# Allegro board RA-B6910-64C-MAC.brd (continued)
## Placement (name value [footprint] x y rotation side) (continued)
C3171  0.1uF/25V  [C0402]  230.55 144.8 0 bottom
C3172  0.1uF/25V  [C0402]  168.58 162.84 0 bottom
C3173  10uF/6.3V  [C0402]  217.23 179.32 270 top
C3174  0.1uF/25V  [C0402]  153.1 139.32 90 top
C3175  0.1uF/25V  [C0402]  227.56 166.9 0 bottom
C3176  0.1uF/25V  [C0402]  213.53 161.84 180 bottom
C3177  0.1uF/25V  [C0402]  215.55 128.82 180 bottom
C3178  0.1uF/25V  [C0402]  165.53 121.83 0 bottom
C3179  0.1uF/25V  [C0402]  226.56 113.81 0 bottom
C3180  47uF/6.3V  [C0805]  257.11 129.79 0 top
C3181  10uF/6.3V  [C0402]  201.54 130.83 0 bottom
C3182  47uF/6.3V  [C0805]  257.11 125.22 0 top
C3183  0.1uF/25V  [C0402]  221.56 168.86 0 bottom
C3184  0.1uF/25V  [C0402]  191.56 120.85 180 bottom
C3185  0.1uF/25V  [C0402]  199.04 160.32 270 bottom
C3186  0.1uF/25V  [C0402]  165.56 144.86 0 bottom
C3187  0.1uF/25V  [C0402]  176.64 139.73 0 bottom
C3188  0.1uF/25V  [C0402]  188.57 167.84 0 bottom
C3189  0.1uF/25V  [C0402]  181.05 158.33 90 bottom
C3190  1uF/25V  [C0402]  199.54 152.83 0 bottom
C3191  47uF/6.3V  [C0805]  257.11 120.65 0 top
C3192  0.1uF/25V  [C0402]  170.53 160.84 0 bottom
C3194  0.1uF/25V  [C0402]  205.05 167.34 270 bottom
C3195  0.1uF/25V  [C0402]  213.55 132.82 0 bottom
C3196  0.1uF/25V  [C0402]  153.1 137.16 270 top
C3197  0.1uF/25V  [C0402]  213.55 144.82 0 bottom
C3317  0.1uF/25V  [C0402]  213.54 142.82 0 bottom
C3318  0.1uF/25V  [C0402]  211.57 125.83 180 bottom
C3319  0.1uF/25V  [C0402]  183.53 125.83 0 bottom
C3320  0.1uF/25V  [C0402]  181.05 154.33 90 bottom
C3321  0.1uF/25V  [C0402]  181.54 150.83 0 bottom
C3322  0.1uF/25V  [C0402]  209.56 153.85 0 bottom
C3323  0.1uF/25V  [C0402]  187.55 124.81 0 bottom
C3324  0.1uF/25V  [C0402]  181.55 147.83 0 bottom
C3325  0.1uF/25V  [C0402]  213.55 128.83 0 bottom
C3326  0.1uF/25V  [C0402]  213.55 145.82 0 bottom
C3327  0.1uF/25V  [C0402]  181.53 144.83 0 bottom
C3328  0.1uF/25V  [C0402]  189.55 124.83 0 bottom
C3329  0.1uF/25V  [C0402]  205.54 152.83 180 bottom
C3330  0.1uF/25V  [C0402]  213.55 131.82 0 bottom
C3331  0.1uF/25V  [C0402]  181.53 141.83 0 bottom
C3332  0.1uF/25V  [C0402]  195.55 125.83 0 bottom
C3333  0.1uF/25V  [C0402]  213.55 148.82 180 bottom
C3334  0.1uF/25V  [C0402]  181.55 136.87 180 bottom
C3335  0.1uF/25V  [C0402]  190.05 154.33 90 bottom
C3336  0.1uF/25V  [C0402]  203.54 125.83 0 bottom
C3337  0.1uF/25V  [C0402]  213.55 134.82 0 bottom
C3338  0.1uF/25V  [C0402]  181.55 133.87 0 bottom
C3339  0.1uF/25V  [C0402]  213.55 151.82 180 bottom
C3340  0.1uF/25V  [C0402]  205.55 124.82 0 bottom
C3341  0.1uF/25V  [C0402]  181.55 130.85 0 bottom
C3342  0.1uF/25V  [C0402]  188.05 154.33 90 bottom
C3343  0.1uF/25V  [C0402]  213.55 139.82 0 bottom
C3344  0.1uF/25V  [C0402]  209.55 124.82 0 bottom
C3345  0.1uF/25V  [C0402]  181.55 127.85 0 bottom
C3346  0.1uF/25V  [C0402]  213.58 152.85 0 bottom
C3347  0.1uF/25V  [C0402]  184.05 154.33 90 bottom
C3368  104  [C0603]  72.07 193.55 0 bottom
C3369  10uF/25V  [C0805]  58.74 183.51 270 bottom
C3370  X  [C1206]  423.48 56 270 top
C3371  X  [C1206]  420.69 56 270 top
C3420  100uF/6.3V  [C1206]  327.98 199.51 0 top
C3421  0.1uF/25V  [C0402]  192.6 179.96 270 top
C3422  0.1uF/25V  [C0402]  193.61 179.96 270 top
C3423  0.1uF/25V  [C0402]  199.71 174.75 270 bottom
C3424  0.1uF/25V  [C0402]  200.85 174.75 270 bottom
C3425  10uF/6.3V  [C0402]  301.18 211.71 180 top
C3426  1uF/25V  [C0402]  290.46 213.84 180 top
C3427  0.1uF/25V  [C0402]  294.91 212.82 0 top
C3428  103  [C0402]  294.91 211.68 0 top
C3429  102  [C0402]  298.89 200.02 0 top
C3430  0.1uF/25V  [C0402]  292.67 215.14 90 bottom
C3431  100P  [C0402]  295.16 215.11 90 bottom
C3432  103  [C0402]  293.89 215.11 90 bottom
C3433  102  [C0402]  295.85 215.14 0 top
C3434  103  [C0402]  292.8 197.61 90 top
C3435  102  [C0402]  293.94 197.61 90 top
C3436  X  [C0402]  306.34 205.33 180 bottom
C3437  10uF/6.3V  [C0402]  296.3 215.11 270 bottom
C3438  100P  [C0402]  297.45 215.11 270 bottom
C3439  22nF  [C0402]  300.8 215.01 270 top
C3440  1uF/25V  [C0402]  301.18 204.85 0 top
C3441  0.1uF/25V  [C0402]  298.21 205.33 90 top
C3442  103  [C0402]  299.35 205.33 90 top
C3443  1uF/25V  [C0402]  294.78 205.33 90 top
C3444  0.1uF/25V  [C0402]  297.07 205.33 90 top
C3445  103  [C0402]  295.92 205.33 90 top
C3446  103  [C0402]  287.54 209.9 180 bottom
C3447  103  [C0402]  287.54 208.38 180 bottom
C3448  1uF/25V  [C0402]  290.46 204.57 180 top
C3449  0.1uF/25V  [C0402]  290.46 205.71 180 top
C3450  103  [C0402]  287.54 212.82 180 bottom
C3451  103  [C0402]  294.91 207.11 0 top
C3452  1uF/25V  [C0402]  290.46 208 180 top
C3453  0.1uF/25V  [C0402]  290.46 206.86 180 top
C3454  103  [C0402]  294.91 208.25 0 top
C3455  103  [C0402]  287.54 211.05 180 bottom
C3456  1uF/25V  [C0402]  290.46 210.28 180 top
C3457  0.1uF/25V  [C0402]  290.46 209.14 180 top
C3458  103  [C0402]  294.91 209.4 0 top
C3459  1uF/25V  [C0402]  290.46 212.57 180 top
C3460  0.1uF/25V  [C0402]  290.46 211.43 180 top
C3461  103  [C0402]  294.91 210.54 0 top
C3462  10uF/6.3V  [C0402]  321.07 205.76 180 top
C3463  0.1uF/25V  [C0402]  321.07 207.03 180 top
C3464  103  [C0402]  321.07 208.3 180 top
C3465  0.1uF/25V  [C0402]  316.52 201.7 180 top
C3466  X  [C0603]  311.29 202.03 0 bottom
C3467  X  [C0603]  311.29 203.93 0 bottom
C3468  1uF/25V  [C0402]  301.18 213.23 180 top
C3469  0.1uF/25V  [C0402]  301.18 210.56 180 top
C3470  1uF/25V  [C0402]  301.18 208.28 180 top
C3471  0.1uF/25V  [C0402]  301.18 209.42 180 top
C3472  1uF/25V  [C0402]  301.18 205.99 180 top
C3473  0.1uF/25V  [C0402]  301.18 207.13 180 top
C3474  X  [C0402]  309 206.6 0 bottom
C3475  X  [C0402]  43.85 157.99 0 top
C3476  X  [C0402]  43.85 159.26 0 top
C3477  X  [C0402]  43.85 156.84 0 top
C3478  X  [C0402]  45.91 163.45 270 top
C3479  X  [C0402]  40.7 163.7 0 top
C3480  X  [C0402]  116.27 218.56 270 bottom
C3481  X  [C0402]  88.33 203.07 270 top
C3482  X  [C0402]  89.34 203.07 270 top
C3483  X  [C0402]  91.38 203.07 270 top
C3484  X  [C0402]  90.36 203.07 270 top
C3485  X  [C0402]  92.39 203.07 270 top
C3486  X  [C0402]  93.41 203.07 270 top
C3487  X  [C0402]  87.31 203.07 270 top
C3488  104  [C0603]  57.47 206.37 90 bottom
C3489  1uF/25V  [C0805]  65.09 205.99 90 bottom
C3490  10uF/25V  [C0805]  62.42 205.99 90 bottom
C3491  X  [C0402]  70.8 217.29 0 bottom
C3492  X  [C0402]  70.8 212.21 0 bottom
C3493  X  [C0402]  70.8 216.28 0 bottom
C3494  X  [C0402]  70.8 211.2 0 bottom
C3495  X  [C0402]  70.8 210.18 0 bottom
C3496  X  [C0402]  70.8 214.25 0 bottom
C3497  X  [C0402]  70.8 213.23 0 bottom
C3498  X  [C0402]  70.8 215.26 0 bottom
C3499  0.1uF/25V  [C0402]  20.99 191.97 270 bottom
C3500  0.1uF/25V  [C0402]  11.75 191.89 270 bottom
C3501  0.1uF/25V  [C0402]  35.24 194.31 0 bottom
C3502  0.1uF/25V  [C0402]  29.65 191.89 270 bottom
C3503  X  [C0603]  411.29 76.58 0 top
C3504  X  [C0603]  406.46 76.58 180 top
C3505  X  [C0402]  406.08 211.88 180 top
C3506  X  [C0402]  408.24 211.88 0 top
C3507  X  [C0402]  403.92 211.88 0 top
C3508  X  [C0402]  397.45 211.88 180 top
C3509  X  [C0402]  393.13 211.88 180 top
C3510  X  [C0402]  401.76 211.88 180 top
C3511  X  [C0402]  399.61 211.88 0 top
C3512  X  [C0402]  395.29 211.88 0 top
C3513  103  [C0402]  423.61 13.81 270 top
C3514  1uF/25V  [C0402]  394.53 21.71 180 top
C3515  0.1uF/25V  [C0402]  394.53 22.86 180 top
C3516  33uF/10V  [C1206]  387.41 212.95 90 bottom
C3517  0.1uF/25V  [C0402]  32.19 173.61 90 top
C3518  X  [C0402]  33.34 173.61 90 top
C3519  0.1uF/25V  [C0402]  199.61 203.15 270 top
C3520  0.1uF/25V  [C0402]  400.19 101.95 180 top
C3521  102  [C0402]  27.24 165.22 90 bottom
C3522  10uF/6.3V  [C0402]  16.6 165.86 0 bottom
C3523  0.1uF/25V  [C0402]  16.19 147.83 90 top
C3524  0.1uF/25V  [C0402]  30.04 152.63 0 bottom
C3525  0.1uF/25V  [C0402]  18.86 167.26 270 bottom
C3526  0.1uF/25V  [C0402]  31.81 167.38 270 bottom
C3527  10uF/6.3V  [C0402]  31.05 155.32 0 bottom
C3528  10uF/6.3V  [C0402]  32.22 150.37 90 bottom
C3529  0.1uF/25V  [C0402]  32.98 164.46 180 bottom
C3530  0.1uF/25V  [C0402]  16.6 151 0 bottom
C3531  0.1uF/25V  [C0402]  18.99 147.83 90 bottom
C3532  0.1uF/25V  [C0402]  30.95 163.83 0 bottom
C3533  10uF/6.3V  [C0402]  16.6 152.78 0 bottom
C3534  0.1uF/25V  [C0402]  23.56 159 180 bottom
C3535  0.1uF/25V  [C0402]  24.83 155.45 90 bottom
C3536  10uF/6.3V  [C0402]  21.4 167.38 270 bottom
C3537  0.1uF/25V  [C0402]  33.11 156.72 180 bottom
C3538  1uF/25V  [C0402]  19.75 165.35 180 bottom
C3539  10uF/6.3V  [C0402]  32.96 165.73 180 bottom
C3540  0.1uF/25V  [C0402]  24.83 160.53 90 bottom
C3541  0.1uF/25V  [C0402]  16.57 167.64 0 bottom
C3542  0.1uF/25V  [C0402]  33.24 152.02 180 bottom
C3543  0.1uF/25V  [C0402]  27.75 159 180 bottom
C3544  0.1uF/25V  [C0402]  21.53 159 0 bottom
C3545  0.1uF/25V  [C0402]  24.83 157.48 270 bottom
C3546  0.1uF/25V  [C0402]  16.57 154.28 0 bottom
C3547  0.1uF/25V  [C0402]  30.54 147.83 90 top
C3548  1uF/25V  [C0402]  30.95 162.68 180 bottom
C3549  10uF/6.3V  [C0402]  19.65 151.69 180 bottom
C3550  10uF/6.3V  [C0402]  34.48 167.89 180 bottom
C3551  0.1uF/25V  [C0402]  18.99 147.83 90 top
C3552  0.1uF/25V  [C0402]  19.65 152.7 180 bottom
C3553  0.1uF/25V  [C0402]  31.05 154.18 0 bottom
C3554  0.1uF/25V  [C0402]  18.38 164.08 90 bottom
C3555  10uF/6.3V  [C0402]  28.66 150.49 90 bottom
C3556  0.1uF/25V  [C0402]  25.72 159 0 bottom
C3557  1uF/25V  [C0402]  18.5 154.18 270 bottom
C3558  10uF/6.3V  [C0402]  30.67 147.83 90 bottom
C3560  10uF/6.3V  [C0402]  408.09 176.27 90 bottom
C3561  0.1uF/25V  [C0402]  396.81 174.55 180 bottom
C3562  0.1uF/25V  [C0402]  413.19 173.48 180 top
C3563  0.1uF/25V  [C0402]  402.02 177.16 90 bottom
C3564  0.1uF/25V  [C0402]  393 189.35 270 bottom
C3565  10uF/6.3V  [C0402]  413.19 186.31 0 top
C3566  10uF/6.3V  [C0402]  399.12 172.34 90 bottom
C3567  0.1uF/25V  [C0402]  410.02 189.23 270 bottom
C3568  0.1uF/25V  [C0402]  393.76 174.62 0 bottom
C3569  0.1uF/25V  [C0402]  405.83 172.34 90 bottom
C3570  0.1uF/25V  [C0402]  410.27 186.31 180 bottom
C3571  10uF/6.3V  [C0402]  396.81 173.53 180 bottom
C3572  0.1uF/25V  [C0402]  393.76 177.06 0 bottom
C3573  1uF/25V  [C0402]  395.67 176.02 270 bottom
C3574  10uF/6.3V  [C0402]  396.05 189.1 270 bottom
C3575  10uF/6.3V  [C0402]  410.4 173.86 180 bottom
C3576  0.1uF/25V  [C0402]  393.76 172.84 0 bottom
C3577  0.1uF/25V  [C0402]  395.54 185.93 90 bottom
C3578  0.1uF/25V  [C0402]  390.84 174.37 0 top
C3579  0.1uF/25V  [C0402]  410.27 178.56 180 bottom
C3580  0.1uF/25V  [C0402]  409.38 172.21 90 bottom
C3581  0.1uF/25V  [C0402]  402.02 182.37 90 bottom
C3582  0.1uF/25V  [C0402]  400.85 180.82 180 bottom
C3583  0.1uF/25V  [C0402]  398.82 180.82 0 bottom
C3584  0.1uF/25V  [C0402]  404.91 180.82 180 bottom
C3585  0.1uF/25V  [C0402]  402.88 180.82 0 bottom
C3586  1uF/25V  [C0402]  408.11 184.53 180 bottom
C3587  10uF/6.3V  [C0402]  396.18 169.67 90 top
C3588  10uF/6.3V  [C0402]  396.94 187.32 180 bottom
C3589  0.1uF/25V  [C0402]  407.2 174.47 0 bottom
C3590  0.1uF/25V  [C0402]  413.19 186.31 180 bottom
C3591  0.1uF/25V  [C0402]  407.1 187.32 0 bottom
C3592  0.1uF/25V  [C0402]  393.76 187.7 0 bottom
C3593  10uF/6.3V  [C0402]  413.19 170.56 180 top
C3594  0.1uF/25V  [C0402]  401.99 179.3 270 bottom
C3595  1uF/25V  [C0402]  409.11 176.27 270 bottom
C3596  10uF/6.3V  [C0402]  408.11 185.67 0 bottom
C3597  100uF/6.3V  [C1206]  327.85 167.89 0 top
C3598  100uF/6.3V  [C1206]  328.1 189.61 0 bottom
C3599  100uF/6.3V  [C1206]  327.85 188.59 0 top
C3600  100uF/6.3V  [C1206]  327.85 178.31 0 top
C3601  100uF/6.3V  [C1206]  327.98 196.72 0 top
C3602  104  [C0603]  384.37 198.75 90 bottom
C3603  0.47uF  [C0603]  279.21 217.68 90 top
C3604  10uF/25V  [C0805]  272.48 213.87 270 top
C3605  0.1uF/25V  [C0402]  275.4 213.99 270 top
C3606  0.47uF  [C0603]  279.46 207.64 90 top
C3607  X  [C0402]  391.99 198.88 270 top
C3608  1uF/25V  [C0402]  274.26 213.99 270 top
C3609  0.1uF/25V  [C0402]  273.24 210.31 90 top
C3610  10uF/6.3V  [C0402]  275.78 210.31 90 top
C3611  1uF/25V  [C0402]  274.51 210.31 90 top
C3612  104  [C0603]  380.94 197.74 90 top
C3613  10uF/25V  [C0805]  378.9 197.74 90 bottom
C3614  10uF/25V  [C0805]  378.9 197.74 90 top
C3615  22uF/25V  [C0805]  377.51 202.56 270 bottom
C3616  22uF/25V  [C0805]  379.92 202.56 270 bottom
C3617  1uF/25V  [C0402]  378.78 201.8 270 top
C3618  0.1uF/25V  [C0402]  380.3 201.8 90 top
C3619  104  [C0603]  366.08 117.35 180 bottom
C3620  X  [C0402]  365.95 124.97 0 top
C3621  104  [C0603]  149.16 210.69 90 bottom
C3622  104  [C0603]  367.09 113.92 180 top
C3623  10uF/25V  [C0805]  367.09 111.88 180 top
C3624  10uF/25V  [C0805]  367.09 111.88 180 bottom
C3625  22uF/6.3V  [C0603]  362.65 110.61 0 bottom
C3626  22uF/6.3V  [C0603]  362.65 113.15 0 bottom
C3627  1uF/25V  [C0402]  363.03 111.76 0 top
C3628  0.1uF/25V  [C0402]  363.03 113.28 180 top
C3629  X  [C0402]  154.62 210.56 270 top
C3630  104  [C0603]  145.35 209.67 90 top
C3631  10uF/25V  [C0805]  143.32 209.67 90 bottom
C3632  10uF/25V  [C0805]  143.32 209.67 90 top
C3633  22uF/6.3V  [C0603]  144.97 213.74 270 bottom
C3634  22uF/6.3V  [C0603]  143.19 213.74 270 bottom
C3635  1uF/25V  [C0402]  143.19 213.74 270 top
C3636  0.1uF/25V  [C0402]  144.97 213.61 90 top
C3637  104  [C0603]  378.9 213.61 90 bottom
C3638  X  [C0402]  386.61 212.72 270 top
C3639  104  [C0603]  375.48 212.6 90 top
C3640  10uF/25V  [C0805]  373.44 212.6 90 top
C3641  10uF/25V  [C0805]  373.44 212.6 90 bottom
C3642  22uF/6.3V  [C0603]  374.71 217.04 270 bottom
C3643  22uF/6.3V  [C0603]  372.17 217.04 270 bottom
C3644  1uF/25V  [C0402]  373.32 216.66 270 top
C3645  0.1uF/25V  [C0402]  374.84 216.66 90 top
C3646  X  [C0402]  377.13 194.31 90 bottom
C3647  X  [C0603]  272.48 217.68 270 top
C3648  22uF/6.3V  [C0603]  363.92 204.98 0 bottom
C3649  X  [C0402]  368.11 163.95 270 bottom
C3650  10uF/25V  [C0805]  8.57 126.87 180 bottom
C3651  10uF/25V  [C0805]  36.26 133.86 180 bottom
C3652  1uF/25V  [C0805]  36.26 133.86 0 top
C3653  1uF/25V  [C0805]  8.57 126.87 0 top
C3654  104  [C0603]  42.33 131.7 270 top
C3655  1uF/25V  [C0805]  46.93 131.44 270 bottom
C3656  10uF/25V  [C0805]  46.55 131.44 270 top
C3657  10uF/25V  [C0805]  44.26 131.44 270 top
C3658  10uF/25V  [C0805]  48.83 131.44 270 top
C3659  10uF/25V  [C0805]  44.39 131.44 270 bottom
C3660  10uF/25V  [C0805]  41.85 131.44 270 bottom
C3661  104  [C0603]  14.64 124.71 270 top
C3662  1uF/25V  [C0805]  19.24 124.46 270 bottom
C3663  10uF/25V  [C0805]  21.78 124.46 270 bottom
C3664  10uF/25V  [C0805]  16.7 124.46 270 bottom
C3665  10uF/25V  [C0805]  21.78 124.46 270 top
C3666  10uF/25V  [C0805]  16.7 124.46 270 top
C3667  10uF/25V  [C0805]  19.24 124.46 270 top
C3668  2200pF  [C0603]  34.23 126.49 90 bottom
C3669  2200pF  [C0603]  6.54 119.5 90 bottom
C3670  104  [C0603]  6.54 113.15 270 bottom
C3671  22nF  [C0402]  6.29 109.85 0 bottom
C3672  104  [C0603]  34.23 120.14 270 bottom
C3673  22nF  [C0402]  33.97 116.84 0 bottom
C3674  100uF/6.3V  [C1206]  22.42 110.23 90 bottom
C3675  100uF/6.3V  [C1206]  28.38 110.23 90 top
C3676  100uF/6.3V  [C1206]  23.94 103.38 0 bottom
C3677  100uF/6.3V  [C1206]  25.84 110.23 90 bottom
C3678  100uF/6.3V  [C1206]  25.84 110.23 90 top
C3679  10uF/6.3V  [C0402]  22.7 110.34 90 top
C3680  1uF/25V  [C0402]  21.45 110.34 90 top
C3681  0.1uF/25V  [C0402]  23.81 110.34 90 top
C3682  100uF/6.3V  [C1206]  55.05 112.9 0 top
C3683  100uF/6.3V  [C1206]  55.05 110.36 0 top
C3684  100uF/6.3V  [C1206]  53.53 117.22 90 top
C3685  100uF/6.3V  [C1206]  53.53 117.22 90 bottom
C3686  100uF/6.3V  [C1206]  50.1 117.22 90 bottom
C3687  10uF/6.3V  [C0402]  50.38 117.32 90 top
C3688  1uF/25V  [C0402]  49.14 117.32 90 top
C3689  0.1uF/25V  [C0402]  51.5 117.32 90 top
C3690  102  [C0402]  33.97 123.19 270 top
C3691  102  [C0402]  6.29 116.2 270 top
C3692  10uF/25V  [C0805]  379.92 110.61 270 bottom
C3693  1uF/25V  [C0805]  379.92 110.61 90 top
C3694  10uF/25V  [C0805]  382.59 145.29 0 top
C3695  104  [C0603]  382.08 116.69 0 top
C3696  1uF/25V  [C0805]  382.33 121.28 0 bottom
C3697  10uF/25V  [C0805]  382.33 123.82 0 top
C3698  10uF/25V  [C0805]  382.33 123.82 0 bottom
C3699  10uF/25V  [C0805]  382.33 118.74 0 bottom
C3700  1uF/25V  [C0805]  380.17 134.62 90 top
C3701  10uF/25V  [C0805]  382.33 121.28 0 top
C3702  10uF/25V  [C0805]  382.33 118.74 0 top
C3703  104  [C0603]  382.33 140.69 0 top
C3704  1uF/25V  [C0805]  382.59 145.29 0 bottom
C3705  10uF/25V  [C0805]  382.59 147.83 0 bottom
C3706  10uF/25V  [C0805]  382.59 142.75 0 bottom
C3707  10uF/25V  [C0805]  382.59 142.75 0 top
C3708  10uF/25V  [C0805]  380.17 134.62 270 bottom
C3709  10uF/25V  [C0805]  382.59 147.83 0 top
C3710  2200pF  [C0603]  387.29 108.58 180 bottom
C3711  2200pF  [C0603]  387.54 132.59 180 bottom
C3712  104  [C0603]  393.64 108.58 0 bottom
C3713  22nF  [C0402]  396.94 108.33 90 bottom
C3714  100uF/6.3V  [C1206]  396.56 124.46 180 bottom
C3715  100uF/6.3V  [C1206]  403.29 127.76 0 bottom
C3716  100uF/6.3V  [C1206]  396.56 127.89 180 top
C3717  100uF/6.3V  [C1206]  403.29 127.76 0 top
C3718  100uF/6.3V  [C1206]  396.56 127.89 180 bottom
C3719  10uF/6.3V  [C0402]  396.46 124.74 180 top
C3720  1uF/25V  [C0402]  396.46 123.49 180 top
C3721  0.1uF/25V  [C0402]  396.46 125.85 180 top
C3722  102  [C0402]  390.59 108.33 0 top
C3723  104  [C0603]  393.89 132.59 0 bottom
C3724  22nF  [C0402]  397.19 132.33 90 bottom
C3725  100uF/6.3V  [C1206]  396.81 151.89 180 top
C3726  100uF/6.3V  [C1206]  396.81 148.46 180 bottom
C3727  100uF/6.3V  [C1206]  396.81 154.43 180 bottom
C3728  100uF/6.3V  [C1206]  396.81 151.89 180 bottom
C3729  100uF/6.3V  [C1206]  396.81 154.43 180 top
C3730  10uF/6.3V  [C0402]  396.71 148.74 180 top
C3731  1uF/25V  [C0402]  396.71 147.5 180 top
C3732  0.1uF/25V  [C0402]  396.71 149.86 180 top
C3733  102  [C0402]  390.84 132.33 0 top
C3798  1uF/25V  [C0402]  50.94 138.53 180 top
C3799  5.6P  [C0402]  59.07 135.99 0 top
C3800  102  [C0402]  59.07 139.04 180 top
C3801  102  [C0402]  59.07 143.1 180 top
C3802  5.6P  [C0402]  59.07 140.05 0 top
C3803  22uF/25V  [C0805]  65.21 135.51 180 bottom
C3804  22uF/25V  [C0805]  65.21 146.43 180 bottom
C3805  1uF/25V  [C0805]  70.5 138.2 0 bottom
C3806  22uF/25V  [C0805]  70.42 140.48 0 bottom
C3807  1uF/25V  [C0805]  70.55 148.36 0 bottom
C3808  22uF/25V  [C0805]  70.55 150.64 0 bottom
C3809  0.1uF/25V  [C0402]  69.02 128.14 180 top
C3810  10uF/25V  [C0805]  65.16 130.27 180 bottom
C3811  0.1uF/25V  [C0402]  69.28 139.06 180 top
C3812  10uF/25V  [C0805]  65.21 140.46 180 bottom
C3813  0.1uF/25V  [C0402]  66.43 134.97 270 top
C3814  0.1uF/25V  [C0402]  66.43 145.13 270 top
C3815  1uF/25V  [C0402]  65.8 132.56 180 top
C3816  1uF/25V  [C0402]  65.8 142.72 180 top
C3817  47uF/6.3V  [C0805]  87.39 137.77 180 bottom
C3818  47uF/6.3V  [C0805]  87.39 147.8 180 bottom
C3819  47uF/6.3V  [C0805]  87.39 140.05 180 bottom
C3820  47uF/6.3V  [C0805]  87.39 129.89 180 bottom
C3821  1uF/25V  [C0402]  50.94 158.85 180 top
C3822  5.6P  [C0402]  59.07 156.31 0 top
C3823  102  [C0402]  59.07 159.36 180 top
C3824  102  [C0402]  59.07 163.42 180 top
C3825  5.6P  [C0402]  59.07 160.37 0 top
C3826  22uF/25V  [C0805]  65.21 166.49 180 bottom
C3827  1uF/25V  [C0805]  65.21 156.21 180 bottom
C3828  22uF/25V  [C0805]  70.55 158.52 0 bottom
C3829  22uF/25V  [C0805]  70.55 160.8 0 bottom
C3830  1uF/25V  [C0805]  70.42 171.07 0 bottom
C3831  22uF/25V  [C0805]  70.42 168.78 0 bottom
C3832  0.1uF/25V  [C0402]  69.28 149.22 180 top
C3833  10uF/25V  [C0805]  65.21 150.62 180 bottom
C3834  0.1uF/25V  [C0402]  69.28 159.26 180 top
C3835  10uF/25V  [C0805]  65.21 161.03 180 bottom
C3836  0.1uF/25V  [C0402]  66.43 155.29 270 top
C3837  0.1uF/25V  [C0402]  66.43 165.45 270 top
C3838  1uF/25V  [C0402]  65.8 152.88 180 top
C3839  1uF/25V  [C0402]  65.8 163.04 180 top
C3840  47uF/6.3V  [C0805]  87.39 170.53 180 bottom
C3841  47uF/6.3V  [C0805]  87.39 168.12 180 bottom
C3842  47uF/6.3V  [C0805]  87.39 160.37 180 bottom
C3843  47uF/6.3V  [C0805]  87.39 150.21 180 bottom
C3844  1uF/25V  [C0402]  50.94 179.17 180 top
C3845  5.6P  [C0402]  59.07 176.63 0 top
C3846  102  [C0402]  59.07 179.68 180 top
C3847  102  [C0402]  59.07 183.74 180 top
C3848  5.6P  [C0402]  59.07 180.69 0 top
C3849  1uF/25V  [C0805]  65.21 176.65 180 bottom
C3850  22uF/25V  [C0805]  70.55 178.94 0 bottom
C3851  1uF/25V  [C0805]  65.21 185.8 180 bottom
C3852  22uF/25V  [C0805]  72.07 191.39 0 bottom
C3853  22uF/25V  [C0805]  70.55 181.23 0 bottom
C3854  22uF/25V  [C0805]  72.07 189.1 0 bottom
C3855  0.1uF/25V  [C0402]  69.28 169.42 180 top
C3856  10uF/25V  [C0805]  65.21 171.07 180 bottom
C3857  0.1uF/25V  [C0402]  69.28 179.58 180 top
C3858  10uF/25V  [C0805]  65.21 181.23 180 bottom
C3859  0.1uF/25V  [C0402]  66.43 175.61 270 top
C3860  0.1uF/25V  [C0402]  66.43 185.77 270 top
C3861  1uF/25V  [C0402]  65.8 173.2 180 top
C3862  1uF/25V  [C0402]  65.8 183.36 180 top
C3863  47uF/6.3V  [C0805]  87.39 180.69 180 bottom
C3864  47uF/6.3V  [C0805]  87.39 178.41 180 bottom
C3865  47uF/6.3V  [C0805]  87.39 188.44 180 bottom
C3866  47uF/6.3V  [C0805]  87.36 190.88 180 bottom
C3867  1uF/25V  [C0402]  363.54 139.82 0 top
C3868  5.6P  [C0402]  355.48 142.52 180 top
C3869  102  [C0402]  355.48 139.47 0 top
C3870  102  [C0402]  355.48 135.4 0 top
C3871  5.6P  [C0402]  355.48 138.45 180 top
C3872  22uF/25V  [C0805]  345.6 178.43 180 bottom
C3873  1uF/25V  [C0805]  350.88 181.12 0 bottom
C3874  22uF/25V  [C0805]  345.67 176.14 180 bottom
C3875  1uF/25V  [C0805]  345.55 168.27 180 bottom
C3876  22uF/25V  [C0805]  350.88 170.2 0 bottom
C3877  22uF/25V  [C0805]  345.55 165.98 180 bottom
C3878  0.1uF/25V  [C0402]  346.82 147.21 0 top
C3879  10uF/25V  [C0805]  350.88 166.01 0 bottom
C3880  0.1uF/25V  [C0402]  346.82 137.05 0 top
C3881  10uF/25V  [C0805]  350.88 176.17 0 bottom
C3882  0.1uF/25V  [C0402]  349.66 141.02 90 top
C3883  0.1uF/25V  [C0402]  349.66 130.86 90 top
C3884  1uF/25V  [C0402]  350.3 143.43 0 top
C3885  1uF/25V  [C0402]  350.3 133.27 0 top
C3886  47uF/6.3V  [C0805]  327.31 156.26 0 bottom
C3887  47uF/6.3V  [C0805]  327.6 127.38 0 bottom
C3888  47uF/6.3V  [C0805]  327.31 135.94 0 bottom
C3889  47uF/6.3V  [C0805]  327.6 124.84 0 bottom
C3890  1uF/25V  [C0402]  363.33 160.04 0 top
C3891  5.6P  [C0402]  355.48 162.84 180 top
C3892  102  [C0402]  355.48 159.79 0 top
C3893  102  [C0402]  355.48 155.72 0 top
C3894  5.6P  [C0402]  355.48 158.77 180 top
C3895  22uF/25V  [C0805]  345.55 155.82 180 bottom
C3896  22uF/25V  [C0805]  345.55 158.11 180 bottom
C3897  22uF/25V  [C0805]  345.67 145.56 180 bottom
C3898  1uF/25V  [C0805]  350.88 150.14 0 bottom
C3899  1uF/25V  [C0805]  345.67 147.85 180 bottom
C3900  22uF/25V  [C0805]  350.88 139.98 0 bottom
C3901  0.1uF/25V  [C0402]  346.82 167.41 0 top
C3902  10uF/25V  [C0805]  350.93 186.36 0 bottom
C3903  0.1uF/25V  [C0402]  346.82 157.37 0 top
C3904  10uF/25V  [C0805]  350.88 155.6 0 bottom
C3905  0.1uF/25V  [C0402]  349.66 161.34 90 top
C3906  0.1uF/25V  [C0402]  349.66 151.18 90 top
C3907  1uF/25V  [C0402]  350.3 163.75 0 top
C3908  1uF/25V  [C0402]  350.3 153.59 0 top
C3909  47uF/6.3V  [C0805]  327.31 146.1 0 bottom
C3910  47uF/6.3V  [C0805]  327.31 138.22 0 bottom
C3911  47uF/6.3V  [C0805]  327.31 158.67 0 bottom
C3912  47uF/6.3V  [C0805]  327.31 148.38 0 bottom
C3913  1uF/25V  [C0402]  363.28 180.85 0 top
C3914  5.6P  [C0402]  355.48 183.16 180 top
C3915  102  [C0402]  355.48 180.11 0 top
C3916  102  [C0402]  355.48 176.04 0 top
C3917  5.6P  [C0402]  355.48 179.09 180 top
C3918  1uF/25V  [C0805]  350.88 130.83 0 bottom
C3919  22uF/25V  [C0805]  343.84 126.91 180 bottom
C3920  22uF/25V  [C0805]  350.88 160.42 0 bottom
C3921  1uF/25V  [C0805]  345.55 137.77 180 bottom
C3922  22uF/25V  [C0805]  343.84 124.62 180 bottom
C3923  22uF/25V  [C0805]  345.55 135.4 180 bottom
C3924  0.1uF/25V  [C0402]  346.82 177.57 0 top
C3925  10uF/25V  [C0805]  350.88 135.4 0 bottom
C3926  0.1uF/25V  [C0402]  347.07 188.49 0 top
C3927  10uF/25V  [C0805]  350.88 145.56 0 bottom
C3928  0.1uF/25V  [C0402]  349.66 181.66 90 top
C3929  0.1uF/25V  [C0402]  349.66 171.5 90 top
C3930  1uF/25V  [C0402]  350.3 173.91 0 top
C3931  1uF/25V  [C0402]  350.3 184.07 0 top
C3932  47uF/6.3V  [C0805]  327.31 166.42 0 bottom
C3933  47uF/6.3V  [C0805]  327.31 178.86 0 bottom
C3934  47uF/6.3V  [C0805]  327.31 168.83 0 bottom
C3935  47uF/6.3V  [C0805]  327.31 176.58 0 bottom
C3936  0.1uF/25V  [C0402]  374.1 161.9 90 top
C3937  0.1uF/25V  [C0402]  373.09 161.9 270 top
C3938  102  [C0402]  381.39 171.7 0 top
C3939  102  [C0402]  382.84 170.3 270 top
C3940  103  [C0402]  379.67 161.92 270 top
C3941  102  [C0402]  382.84 168.15 270 top
C3942  1uF/25V  [C0402]  377.79 170.53 0 bottom
C3943  4.7uF  [C0603]  376.49 172.97 90 top
C3944  102  [C0402]  382.84 166.06 270 top
C3945  1uF/25V  [C0402]  379.03 172.34 270 bottom
C3946  102  [C0402]  382.87 163.8 270 top
C3947  102  [C0402]  382.87 161.64 270 top
C3948  100P  [C0402]  375.02 172.57 90 top
C3949  100P  [C0402]  373.85 172.57 90 top
C3950  3.3nF  [C0402]  378.55 172.18 0 top
C3951  3.3nF  [C0402]  381.32 161.01 0 top
CD1  220uF/25V  [CDNCC_0810]  46.8 201.17 0 top
CD16  220uF/25V  [CDNCC_0810]  247.97 206.63 90 top
CD47  330uF/2V  [CDRUB_7M3X4M3]  328.1 192.53 180 top
CD48  330uF/2V  [CDRUB_7M3X4M3]  328.1 193.8 180 bottom
CD58  330uf/16V  [CDNCC_10M30X12M2]  363.96 188.24 180 top
CD59  330uf/16V  [CDNCC_10M30X12M2]  53.15 170.69 0 top
CD60  330uf/16V  [CDNCC_10M30X12M2]  364.09 150.01 180 top
CD61  330uf/16V  [CDNCC_10M30X12M2]  47.82 187.96 0 top
CD62  330uf/16V  [CDNCC_10M30X12M2]  363.96 169.95 180 top
CD63  220uF/25V  [CDNCC_0810]  77.28 201.17 180 top
CD64  330uf/16V  [CDNCC_10M30X12M2]  53.15 149.8 0 top
CD65  220uF/25V  [CDNCC_0810]  44.11 138.43 180 top
CD66  220uF/25V  [CDNCC_0810]  23.18 131.32 180 top
CD67  220uF/25V  [CDNCC_0810]  375.35 119.38 270 top
CD68  220uF/25V  [CDNCC_0810]  375.6 143.38 270 top
CD69  330uF/2V  [CDRUB_7M3X4M3]  87.39 143.86 0 bottom
CD70  330uF/2V  [CDRUB_7M3X4M3]  87.39 133.7 0 bottom
CD71  330uF/2V  [CDRUB_7M3X4M3]  87.39 164.18 0 bottom
CD72  330uF/2V  [CDRUB_7M3X4M3]  87.39 154.02 0 bottom
CD73  330uF/2V  [CDRUB_7M3X4M3]  87.39 184.5 0 bottom
CD74  330uF/2V  [CDRUB_7M3X4M3]  87.39 174.34 0 bottom
CD75  330uF/2V  [CDRUB_7M3X4M3]  328.45 142.29 180 bottom
CD76  330uF/2V  [CDRUB_7M3X4M3]  328.45 132.13 180 bottom
CD77  330uF/2V  [CDRUB_7M3X4M3]  328.45 152.45 180 bottom
CD78  330uF/2V  [CDRUB_7M3X4M3]  328.45 162.61 180 bottom
CD79  330uF/2V  [CDRUB_7M3X4M3]  328.45 182.93 180 bottom
CD80  330uF/2V  [CDRUB_7M3X4M3]  328.45 172.77 180 bottom
D92  SRV05_4TCT  [SOT_23_6]  410.27 55.12 90 top
D93  SRV05_4TCT  [SOT_23_6]  402.65 55.12 90 top
D94  SRV05_4TCT  [SOT_23_6]  389.06 25.4 0 bottom
D363  EVERLIGHT 18-225R6G6C-A013T  [LED_2_GR]  15 48.59 90 top
D364  EVERLIGHT 18-225R6G6C-A013T  [LED_2_GR]  109 48.59 90 top
D365  EVERLIGHT 18-225R6G6C-A013T  [LED_2_GR]  203 48.59 90 top
D366  EVERLIGHT 18-225R6G6C-A013T  [LED_2_GR]  297 48.59 90 top
D367  EVERLIGHT 18-225R6G6C-A013T  [LED_2_GR]  32 48.59 90 top
D368  EVERLIGHT 18-225R6G6C-A013T  [LED_2_GR]  126 48.59 90 top
D369  EVERLIGHT 18-225R6G6C-A013T  [LED_2_GR]  220 48.59 90 top
D370  EVERLIGHT 18-225R6G6C-A013T  [LED_2_GR]  314 48.59 90 top
D371  EVERLIGHT 18-225R6G6C-A013T  [LED_2_GR]  34 48.59 90 top
D372  EVERLIGHT 18-225R6G6C-A013T  [LED_2_GR]  128 48.59 90 top
D373  EVERLIGHT 18-225R6G6C-A013T  [LED_2_GR]  316 48.59 90 top
D374  EVERLIGHT 18-225R6G6C-A013T  [LED_2_GR]  222 48.59 90 top
D375  EVERLIGHT 18-225R6G6C-A013T  [LED_2_GR]  51 48.59 90 top
D376  EVERLIGHT 18-225R6G6C-A013T  [LED_2_GR]  239 48.59 90 top
D377  EVERLIGHT 18-225R6G6C-A013T  [LED_2_GR]  333 48.59 90 top
D378  EVERLIGHT 18-225R6G6C-A013T  [LED_2_GR]  145 48.59 90 top
D379  EVERLIGHT 18-225R6G6C-A013T  [LED_2_GR]  62 48.59 90 top
D380  EVERLIGHT 18-225R6G6C-A013T  [LED_2_GR]  156 48.59 90 top
D381  EVERLIGHT 18-225R6G6C-A013T  [LED_2_GR]  344 48.59 90 top
D382  EVERLIGHT 18-225R6G6C-A013T  [LED_2_GR]  250 48.59 90 top
D383  EVERLIGHT 18-225R6G6C-A013T  [LED_2_GR]  79 48.59 90 top
D384  EVERLIGHT 18-225R6G6C-A013T  [LED_2_GR]  267 48.59 90 top
D385  EVERLIGHT 18-225R6G6C-A013T  [LED_2_GR]  173 48.59 90 top
D386  EVERLIGHT 18-225R6G6C-A013T  [LED_2_GR]  361 48.59 90 top
D387  EVERLIGHT 18-225R6G6C-A013T  [LED_2_GR]  81 48.59 90 top
D388  EVERLIGHT 18-225R6G6C-A013T  [LED_2_GR]  175 48.59 90 top
D389  EVERLIGHT 18-225R6G6C-A013T  [LED_2_GR]  269 48.59 90 top
D390  EVERLIGHT 18-225R6G6C-A013T  [LED_2_GR]  363 48.59 90 top
D391  EVERLIGHT 18-225R6G6C-A013T  [LED_2_GR]  98 48.59 90 top
D392  EVERLIGHT 18-225R6G6C-A013T  [LED_2_GR]  192 48.59 90 top
D393  EVERLIGHT 18-225R6G6C-A013T  [LED_2_GR]  286 48.59 90 top
D394  EVERLIGHT 18-225R6G6C-A013T  [LED_2_GR]  380 48.59 90 top
D395  EVERLIGHT 18-225R6G6C-A013T  [LED_2_GR]  15.4 48.59 90 bottom
D396  EVERLIGHT 18-225R6G6C-A013T  [LED_2_GR]  109.4 48.59 90 bottom
D397  EVERLIGHT 18-225R6G6C-A013T  [LED_2_GR]  203.4 48.59 90 bottom
D398  EVERLIGHT 18-225R6G6C-A013T  [LED_2_GR]  297.4 48.59 90 bottom
D399  EVERLIGHT 18-225R6G6C-A013T  [LED_2_GR]  32.4 48.59 90 bottom
D400  EVERLIGHT 18-225R6G6C-A013T  [LED_2_GR]  126.4 48.59 90 bottom
D401  EVERLIGHT 18-225R6G6C-A013T  [LED_2_GR]  314.4 48.59 90 bottom
D402  EVERLIGHT 18-225R6G6C-A013T  [LED_2_GR]  220.4 48.59 90 bottom
D403  EVERLIGHT 18-225R6G6C-A013T  [LED_2_GR]  34.4 48.59 90 bottom
D404  EVERLIGHT 18-225R6G6C-A013T  [LED_2_GR]  128.4 48.59 90 bottom
D405  EVERLIGHT 18-225R6G6C-A013T  [LED_2_GR]  222.4 48.59 90 bottom
D406  EVERLIGHT 18-225R6G6C-A013T  [LED_2_GR]  316.4 48.59 90 bottom
D407  EVERLIGHT 18-225R6G6C-A013T  [LED_2_GR]  51.4 48.59 90 bottom
D408  EVERLIGHT 18-225R6G6C-A013T  [LED_2_GR]  333.4 48.59 90 bottom
D409  EVERLIGHT 18-225R6G6C-A013T  [LED_2_GR]  239.4 48.59 90 bottom
D410  EVERLIGHT 18-225R6G6C-A013T  [LED_2_GR]  145.4 48.59 90 bottom
D411  EVERLIGHT 18-225R6G6C-A013T  [LED_2_GR]  62.4 48.59 90 bottom
D412  EVERLIGHT 18-225R6G6C-A013T  [LED_2_GR]  156.4 48.59 90 bottom
D413  EVERLIGHT 18-225R6G6C-A013T  [LED_2_GR]  250.4 48.59 90 bottom
D414  EVERLIGHT 18-225R6G6C-A013T  [LED_2_GR]  344.4 48.59 90 bottom
D415  EVERLIGHT 18-225R6G6C-A013T  [LED_2_GR]  79.4 48.59 90 bottom
D416  EVERLIGHT 18-225R6G6C-A013T  [LED_2_GR]  173.4 48.59 90 bottom
D417  EVERLIGHT 18-225R6G6C-A013T  [LED_2_GR]  361.4 48.59 90 bottom
D418  EVERLIGHT 18-225R6G6C-A013T  [LED_2_GR]  267.4 48.59 90 bottom
D419  EVERLIGHT 18-225R6G6C-A013T  [LED_2_GR]  81.4 48.59 90 bottom
D420  EVERLIGHT 18-225R6G6C-A013T  [LED_2_GR]  175.4 48.59 90 bottom
D421  EVERLIGHT 18-225R6G6C-A013T  [LED_2_GR]  269.4 48.59 90 bottom
D422  EVERLIGHT 18-225R6G6C-A013T  [LED_2_GR]  363.4 48.59 90 bottom
D423  EVERLIGHT 18-225R6G6C-A013T  [LED_2_GR]  98.4 48.59 90 bottom
D424  EVERLIGHT 18-225R6G6C-A013T  [LED_2_GR]  192.4 48.59 90 bottom
D425  EVERLIGHT 18-225R6G6C-A013T  [LED_2_GR]  286.4 48.59 90 bottom
D426  EVERLIGHT 18-225R6G6C-A013T  [LED_2_GR]  380.4 48.59 90 bottom
D427  17_21_G6C_FM1N2B_3T  [LED_SMT0805]  40.32 173.1 270 top
D428  17_21_G6C_FM1N2B_3T  [LED_SMT0805]  410.65 193.8 270 top
D429  EVERLIGHT 18-225R6G6C-A013T  [LED_2_GR]  391 65 90 top
D430  EVERLIGHT 18-225R6G6C-A013T  [LED_2_GR]  398 65 90 top
D431  EVERLIGHT 18-225R6G6C-A013T  [LED_2_GR]  405 65 90 top
D432  EVERLIGHT 18-225R6G6C-A013T  [LED_2_GR]  412 65 90 top
D433  LS_SP190YG84_5  [LED_SMT0603]  419 65 90 top
D434  17_21_G6C_FM1N2B_3T  [LED_SMT0805]  370.4 208.15 180 top
D435  ISL99227BFRZ-T  [ISL99227B]  70.75 133.2 90 top
D436  ISL99227BFRZ-T  [ISL99227B]  70.75 143.36 90 top
D437  ISL99227BFRZ-T  [ISL99227B]  70.75 153.52 90 top
D438  ISL99227BFRZ-T  [ISL99227B]  70.75 163.68 90 top
D439  ISL99227BFRZ-T  [ISL99227B]  70.75 173.84 90 top
D440  ISL99227BFRZ-T  [ISL99227B]  70.75 184 90 top
D441  ISL99227BFRZ-T  [ISL99227B]  345.34 132.63 270 top
D442  ISL99227BFRZ-T  [ISL99227B]  345.34 142.79 270 top
D443  ISL99227BFRZ-T  [ISL99227B]  345.34 163.11 270 top
D444  ISL99227BFRZ-T  [ISL99227B]  345.34 152.95 270 top
D445  ISL99227BFRZ-T  [ISL99227B]  345.34 183.43 270 top
D446  ISL99227BFRZ-T  [ISL99227B]  345.34 173.27 270 top
FD1  -  [MARK]  389.57 38.86 0 top
FD2  -  [MARK]  21.1 75.84 0 top
FD3  -  [MARK]  413.73 213.85 0 top
FD4  -  [MARK]  13.4 202.94 0 top
FD5  -  [MARK]  389.57 38.86 180 bottom
FD6  -  [MARK]  13.4 202.94 180 bottom
FD7  -  [MARK]  21.53 86.61 180 bottom
FD8  -  [MARK]  413.73 213.85 180 bottom
J18  1125_1103SNR23801  [1125_1103SN]  424.62 193.8 90 top
J29  USB_CP05AP0_04F  [USB_A_09F]  393.5 11.5 180 top
J30  -  [3110_10G0BK00T1]  403.29 202.69 0 top
J33  -  [3110_10G0BK00T1]  14.29 193.42 0 top
J34  -  [3110_10G0BK00T1]  33.34 191.77 270 top
J35  -  [C200126080S9001R]  395.3 220.25 180 top
L24  300/2A  [L0805]  164.15 179.07 90 top
L26  1.5uH/9A  [L_7M2X6M5X3]  250.69 216.1 0 top
L30  600/500mA  [L0603]  177.1 179.07 90 top
L31  600/500mA  [L0603]  162.37 185.29 90 top
L32  300/2A  [L0805]  211.14 196.85 90 top
L33  300/2A  [L0805]  174.31 185.29 90 top
L34  300/2A  [L0805]  208.72 196.85 90 top
L35  300/2A  [L0805]  169.1 191.64 90 top
L36  300/2A  [L0805]  155.89 173.06 90 top
L37  300/2A  [L0805]  157.16 162.43 90 top
L38  300/2A  [L0805]  154.88 162.43 90 top
L39  300/2A  [L0805]  157.16 149.73 90 top
L40  300/2A  [L0805]  154.88 149.73 90 top
L41  300/2A  [L0805]  155.26 137.41 90 top
L42  300/2A  [L0805]  157.54 137.41 90 top
L43  300/2A  [L0805]  154.88 123.44 90 top
L44  300/2A  [L0805]  157.16 123.44 90 top
L45  300/2A  [L0805]  173.8 98.93 0 top
L46  300/2A  [L0805]  173.8 101.22 0 top
L47  300/2A  [L0805]  188.79 98.93 0 top
L48  300/2A  [L0805]  188.79 101.22 0 top
L49  300/2A  [L0805]  201.61 98.93 0 top
L50  300/2A  [L0805]  201.61 101.22 0 top
L51  300/2A  [L0805]  220.66 101.22 0 top
L52  300/2A  [L0805]  220.66 96.64 0 top
L53  300/2A  [L0805]  240.22 128.39 90 top
L54  300/2A  [L0805]  237.93 128.39 90 top
L55  300/2A  [L0805]  241.24 142.11 90 top
L56  300/2A  [L0805]  238.95 142.11 90 top
L57  300/2A  [L0805]  239.46 154.43 90 top
L58  300/2A  [L0805]  237.17 154.43 90 top
L59  300/2A  [L0805]  240.22 166.62 90 top
L60  300/2A  [L0805]  237.93 166.62 90 top
L61  300/2A  [L0805]  214.82 196.85 90 top
L62  300/2A  [L0805]  229.3 196.85 90 top
L63  300/2A  [L0805]  222.06 196.85 90 top
L64  300/2A  [L0805]  217.23 196.85 90 top
L65  BPH853225W4-101T  [L_9M00X3M10X2M80]  147.64 155.45 180 bottom
L66  100/10A  [74279225101]  147.76 150.31 180 bottom
L67  100/10A  [74279225101]  147.76 161.29 180 bottom
L69  BPH853225W4-101T  [L_9M00X3M10X2M80]  147.51 126.49 180 bottom
L70  100/10A  [74279225101]  147.05 133.35 180 bottom
L71  100/10A  [74279225101]  147.05 119.02 180 bottom
L73  BPH853225W4-101T  [L_9M00X3M10X2M80]  244.16 113.41 0 bottom
L74  100/10A  [74279225101]  243.78 118.11 0 bottom
L75  100/10A  [74279225101]  243.68 108.96 0 bottom
L77  BPH853225W4-101T  [L_9M00X3M10X2M80]  246.42 154.68 0 bottom
L78  100/10A  [74279225101]  247.08 143.13 0 bottom
L79  100/10A  [74279225101]  246.42 166.67 0 bottom
L222  300/2A  [L0805]  394.4 27.43 0 top
L226  200nH/50A  [L_11M50X7M00X9M20]  60.64 201.67 180 top
L228  300/2A  [L0805]  45.4 81.91 0 top
L229  300/2A  [L0805]  32.7 100.33 180 top
L230  300/2A  [L0805]  13.4 78.61 180 top
L231  300/2A  [L0805]  8.95 84.45 0 top
L232  300/2A  [L0805]  45.4 87.75 0 bottom
L233  300/2A  [L0805]  32.7 94.49 180 top
L234  300/2A  [L0805]  13.4 84.45 180 bottom
L235  300/2A  [L0805]  8.95 78.61 0 bottom
L236  300/2A  [L0805]  28.13 94.49 0 bottom
L237  300/2A  [L0805]  28.13 100.33 0 bottom
L238  300/2A  [L0805]  49.97 81.91 180 bottom
L239  300/2A  [L0805]  49.97 86.48 180 top
L240  300/2A  [L0805]  8.95 84.45 0 bottom
L241  300/2A  [L0805]  13.4 78.61 180 bottom
L242  300/2A  [L0805]  32.7 100.33 180 bottom
L243  300/2A  [L0805]  45.4 81.91 0 bottom
L244  300/2A  [L0805]  8.95 78.61 0 top
L245  300/2A  [L0805]  13.4 84.45 180 top
L246  300/2A  [L0805]  32.7 94.49 180 bottom
L247  300/2A  [L0805]  37.91 94.49 0 bottom
L248  300/2A  [L0805]  28.13 94.49 0 top
L249  300/2A  [L0805]  28.13 100.33 0 top
L250  300/2A  [L0805]  49.97 87.75 180 bottom
L251  300/2A  [L0805]  49.97 81.91 180 top
L252  300/2A  [L0805]  89.6 81.91 0 top
L253  300/2A  [L0805]  80.84 81.91 180 top
L254  300/2A  [L0805]  67.63 81.91 180 bottom
L255  300/2A  [L0805]  63.18 81.91 0 bottom
L256  300/2A  [L0805]  89.6 87.75 0 top
L257  300/2A  [L0805]  80.84 87.75 180 top
L258  300/2A  [L0805]  67.63 87.75 180 top
L259  300/2A  [L0805]  63.18 87.75 0 bottom
L260  300/2A  [L0805]  94.17 87.75 180 top
L261  300/2A  [L0805]  76.39 87.75 0 bottom
L262  300/2A  [L0805]  94.17 81.91 180 top
L263  300/2A  [L0805]  76.39 81.91 0 bottom
L264  300/2A  [L0805]  63.18 81.91 0 top
L265  300/2A  [L0805]  67.63 81.91 180 top
L266  300/2A  [L0805]  80.84 81.91 180 bottom
L267  300/2A  [L0805]  89.6 81.91 0 bottom
L268  300/2A  [L0805]  63.18 87.75 0 top
L269  300/2A  [L0805]  67.63 87.75 180 bottom
L270  300/2A  [L0805]  80.84 87.75 180 bottom
L271  300/2A  [L0805]  89.6 87.75 0 bottom
L272  300/2A  [L0805]  76.39 87.75 0 top
L273  300/2A  [L0805]  94.17 87.75 180 bottom
L274  300/2A  [L0805]  76.39 81.91 0 top
L275  300/2A  [L0805]  98.74 87.75 0 bottom
L276  300/2A  [L0805]  139.76 87.75 0 bottom
L277  300/2A  [L0805]  130.62 87.75 180 top
L278  300/2A  [L0805]  117.41 81.91 180 bottom
L279  300/2A  [L0805]  108.52 87.75 180 bottom
L280  300/2A  [L0805]  139.38 81.91 0 bottom
L281  300/2A  [L0805]  130.62 81.91 180 top
L282  300/2A  [L0805]  117.41 87.75 180 top
L283  300/2A  [L0805]  112.97 87.75 0 bottom
L284  300/2A  [L0805]  143.95 81.91 180 bottom
L285  300/2A  [L0805]  136.59 93.47 90 bottom
L286  300/2A  [L0805]  126.17 81.91 0 bottom
L287  300/2A  [L0805]  126.17 87.75 0 bottom
L288  300/2A  [L0805]  112.97 81.91 0 top
L289  300/2A  [L0805]  117.41 81.91 180 top
L290  300/2A  [L0805]  130.62 87.75 180 bottom
L291  300/2A  [L0805]  139.38 87.75 0 top
L292  300/2A  [L0805]  112.97 87.75 0 top
L293  300/2A  [L0805]  117.41 87.75 180 bottom
L294  300/2A  [L0805]  130.62 81.91 180 bottom
L295  300/2A  [L0805]  139.38 81.91 0 top
L296  300/2A  [L0805]  126.17 87.75 0 top
L297  300/2A  [L0805]  143.95 87.75 180 top
L298  300/2A  [L0805]  143.95 81.91 180 top
L299  300/2A  [L0805]  126.17 81.91 0 top
L300  300/2A  [L0805]  183.58 81.91 0 top
L301  300/2A  [L0805]  174.82 81.91 180 top
L302  300/2A  [L0805]  161.61 81.91 180 bottom
L303  300/2A  [L0805]  157.16 81.91 0 bottom
L304  300/2A  [L0805]  183.58 87.75 0 top
L305  300/2A  [L0805]  174.82 87.75 180 top
L306  300/2A  [L0805]  161.61 87.75 180 top
L307  300/2A  [L0805]  136.59 98.17 90 bottom
L308  300/2A  [L0805]  192.72 87.75 0 bottom
L309  300/2A  [L0805]  170.37 87.75 0 bottom
L310  300/2A  [L0805]  188.15 87.75 180 bottom
L311  300/2A  [L0805]  170.37 81.91 0 bottom
L312  300/2A  [L0805]  157.16 81.91 0 top
L313  300/2A  [L0805]  161.61 81.91 180 top
L314  300/2A  [L0805]  174.82 81.91 180 bottom
L315  300/2A  [L0805]  183.58 81.91 0 bottom
L316  300/2A  [L0805]  157.16 87.75 0 top
L317  300/2A  [L0805]  161.61 94.61 180 top
L318  300/2A  [L0805]  174.82 87.75 180 bottom
L319  300/2A  [L0805]  183.58 87.75 0 bottom
L320  300/2A  [L0805]  170.37 87.75 0 top
L321  300/2A  [L0805]  188.15 81.91 180 top
L322  300/2A  [L0805]  170.37 81.91 0 top
L323  300/2A  [L0805]  188.15 87.75 180 top
L324  300/2A  [L0805]  233.36 81.91 0 top
L325  300/2A  [L0805]  224.6 87.75 180 top
L326  300/2A  [L0805]  211.39 81.91 180 top
L327  300/2A  [L0805]  206.95 87.75 0 top
L328  300/2A  [L0805]  224.6 92.33 180 bottom
L329  300/2A  [L0805]  224.6 81.91 180 top
L330  300/2A  [L0805]  211.39 87.75 180 bottom
L331  300/2A  [L0805]  201.61 87.88 0 bottom
L332  300/2A  [L0805]  237.93 81.91 180 bottom
L333  300/2A  [L0805]  237.93 87.75 180 top
L334  300/2A  [L0805]  220.15 81.91 0 bottom
L335  300/2A  [L0805]  220.15 87.75 0 bottom
L336  300/2A  [L0805]  206.95 87.75 0 bottom
L337  300/2A  [L0805]  211.39 81.91 180 bottom
L338  300/2A  [L0805]  224.6 87.75 180 bottom
L339  300/2A  [L0805]  233.36 81.91 0 bottom
L340  300/2A  [L0805]  206.95 81.91 0 top
L341  300/2A  [L0805]  211.39 87.75 180 top
L342  300/2A  [L0805]  224.6 81.91 180 bottom
L343  300/2A  [L0805]  233.36 87.75 0 top
L344  300/2A  [L0805]  220.15 87.75 0 top
L345  300/2A  [L0805]  220.15 81.91 0 top
L346  300/2A  [L0805]  251.14 94.61 0 top
L347  300/2A  [L0805]  237.93 81.91 180 top
L348  300/2A  [L0805]  277.56 81.91 0 top
L349  300/2A  [L0805]  268.8 81.91 180 top
L350  300/2A  [L0805]  255.59 81.91 180 bottom
L351  300/2A  [L0805]  251.14 81.91 0 bottom
L352  300/2A  [L0805]  277.56 87.75 0 top
L353  300/2A  [L0805]  268.8 87.75 180 top
L354  300/2A  [L0805]  255.59 87.75 180 top
L355  300/2A  [L0805]  254.57 92.58 90 bottom
L356  300/2A  [L0805]  282.13 87.75 180 top
L357  300/2A  [L0805]  264.35 81.91 0 bottom
L358  300/2A  [L0805]  264.35 87.75 0 bottom
L359  300/2A  [L0805]  282.13 81.91 180 top
L360  300/2A  [L0805]  251.14 81.91 0 top
L361  300/2A  [L0805]  255.59 81.91 180 top
L362  300/2A  [L0805]  268.8 81.91 180 bottom
L363  300/2A  [L0805]  277.56 81.91 0 bottom
L364  300/2A  [L0805]  251.14 87.75 0 top
L365  300/2A  [L0805]  256.86 92.58 90 bottom
L366  300/2A  [L0805]  268.8 87.75 180 bottom
L367  300/2A  [L0805]  277.56 87.75 0 bottom
L368  300/2A  [L0805]  264.35 87.75 0 top
L369  300/2A  [L0805]  286.45 87.75 0 bottom
L370  300/2A  [L0805]  282.13 87.75 180 bottom
L371  300/2A  [L0805]  264.35 81.91 0 top
L372  300/2A  [L0805]  328.99 81.91 0 bottom
L373  300/2A  [L0805]  320.23 87.75 180 bottom
L374  300/2A  [L0805]  304.99 81.91 180 bottom
L375  300/2A  [L0805]  286.45 87.75 0 top
L376  300/2A  [L0805]  328.99 87.75 0 top
L377  300/2A  [L0805]  320.23 81.91 180 bottom
L378  300/2A  [L0805]  304.86 87.88 0 top
L379  300/2A  [L0805]  300.55 81.91 0 top
L380  300/2A  [L0805]  333.57 81.91 180 bottom
L381  300/2A  [L0805]  315.79 87.75 0 bottom
L382  300/2A  [L0805]  333.57 87.75 180 top
L383  300/2A  [L0805]  315.79 81.91 0 bottom
L384  300/2A  [L0805]  300.29 87.88 0 top
L385  300/2A  [L0805]  304.99 81.91 180 top
L386  300/2A  [L0805]  320.23 87.75 180 top
L387  300/2A  [L0805]  328.99 81.91 0 top
L388  300/2A  [L0805]  293.56 86.61 180 top
L389  300/2A  [L0805]  309.44 87.88 180 top
L390  300/2A  [L0805]  320.23 81.91 180 top
L391  300/2A  [L0805]  328.99 87.75 0 bottom
L392  300/2A  [L0805]  333.57 81.91 180 top
L393  300/2A  [L0805]  315.79 87.75 0 top
L394  300/2A  [L0805]  315.79 81.91 0 top
L395  300/2A  [L0805]  333.57 87.75 180 bottom
L396  300/2A  [L0805]  389.57 86.87 180 top
L397  300/2A  [L0805]  375.09 82.17 0 bottom
L398  300/2A  [L0805]  353 81.91 180 bottom
L399  300/2A  [L0805]  348.55 81.91 0 bottom
L400  300/2A  [L0805]  385 86.87 0 top
L401  300/2A  [L0805]  375.09 82.17 0 top
L402  300/2A  [L0805]  351.85 87.75 180 top
L403  300/2A  [L0805]  348.55 87.75 0 bottom
L404  300/2A  [L0805]  385 81.02 0 top
L405  300/2A  [L0805]  389.57 81.02 180 top
L406  300/2A  [L0805]  361.76 81.91 0 bottom
L407  300/2A  [L0805]  366.2 81.91 180 top
L408  300/2A  [L0805]  348.55 81.91 0 top
L409  300/2A  [L0805]  353 81.91 180 top
L410  300/2A  [L0805]  366.2 81.91 180 bottom
L411  300/2A  [L0805]  389.57 86.87 180 bottom
L412  300/2A  [L0805]  347.41 87.75 0 top
L413  300/2A  [L0805]  353 87.75 180 bottom
L414  300/2A  [L0805]  385 94.99 0 top
L415  300/2A  [L0805]  385 86.87 0 bottom
L416  300/2A  [L0805]  359.09 86.48 180 top
L417  300/2A  [L0805]  389.57 81.02 180 bottom
L418  300/2A  [L0805]  385 81.02 0 bottom
L419  300/2A  [L0805]  361.76 81.91 0 top
L422  600/500mA  [L0603]  174.69 191.64 90 top
L425  600/500mA  [L0603]  219.65 196.85 90 top
L426  600/500mA  [L0603]  183.2 179.07 90 top
L428  600/500mA  [L0603]  185.1 195.58 90 top
L430  300/2A  [L0805]  187.52 196.21 90 top
L432  600/500mA  [L0603]  159.7 137.41 90 top
L433  600/500mA  [L0603]  224.47 196.21 90 top
L436  600/500mA  [L0603]  235.14 154.3 90 top
L437  300/2A  [L0805]  162.24 136.4 90 bottom
L438  600/500mA  [L0603]  201.61 96.64 0 top
L439  600/500mA  [L0603]  168.21 185.29 90 top
L440  600/500mA  [L0603]  163.26 191.64 90 top
L441  600/500mA  [L0603]  151.83 137.41 90 top
L442  600/500mA  [L0603]  235.14 142.11 90 top
L444  300/2A  [L0805]  239.71 112.42 90 top
L445  300/2A  [L0805]  231.33 177.54 90 bottom
L446  300/2A  [L0805]  296.48 198.88 270 top
L447  600/500mA  [L0603]  293.18 215.01 180 top
L448  300/2A  [L0805]  317.11 203.68 180 top
L449  X  [L0805]  43.88 162.3 270 top
L450  300/2A  [L0805]  423.61 8.13 90 top
L451  3.3uH/3.8A  [L_7M50X7M50X4M70]  373.82 199.64 270 top
L452  3.3uH/3.8A  [L_7M50X7M50X4M70]  365.19 106.8 0 top
L453  3.3uH/3.8A  [L_7M50X7M50X4M70]  138.11 211.71 270 top
L454  3.3uH/3.8A  [L_7M50X7M50X4M70]  368.36 214.5 270 top
L455  1.0uH/29A  [L_13M50X12M50X4M80]  41.59 116.84 90 top
L456  1.0uH/29A  [L_13M50X12M50X4M80]  13.91 109.85 90 top
L457  1.0uH/29A  [L_13M50X12M50X4M80]  396.94 115.95 180 top
L458  1.0uH/29A  [L_13M50X12M50X4M80]  397.19 139.95 180 top
L491  200nH/50A  [L_11M50X7M00X9M20]  87.13 143.36 0 top
L492  200nH/50A  [L_11M50X7M00X9M20]  87.13 133.2 180 top
L493  200nH/50A  [L_11M50X7M00X9M20]  87.13 163.68 0 top
L494  200nH/50A  [L_11M50X7M00X9M20]  87.13 153.52 180 top
L495  200nH/50A  [L_11M50X7M00X9M20]  87.13 184 0 top
L496  200nH/50A  [L_11M50X7M00X9M20]  87.13 173.84 180 top
L497  200nH/50A  [L_11M50X7M00X9M20]  328.71 132.63 180 top
L498  200nH/50A  [L_11M50X7M00X9M20]  328.71 142.79 0 top
L499  200nH/50A  [L_11M50X7M00X9M20]  328.71 152.95 180 top
L500  200nH/50A  [L_11M50X7M00X9M20]  328.71 162.73 0 top
L501  200nH/50A  [L_11M50X7M00X9M20]  328.71 173.15 180 top
L502  200nH/50A  [L_11M50X7M00X9M20]  328.71 183.43 0 top
NOREF  -  []  286.8 2.95 90 top
NOREF#2  -  []  127.2 51.89 0 top
NOREF#3  -  []  -128.51 313.85 0 top
NOREF#4  -  []  108 25.59 90 top
NOREF#5  -  []  362.96 216.61 90 top
NOREF#6  -  []  121.08 360.47 0 top
NOREF#7  -  []  -57.21 385.86 0 top
NOREF#8  -  []  861.82 123.12 90 top
NOREF#9  -  []  162.95 131.05 90 top
NOREF#10  -  []  249 7.59 90 top
NOREF#11  -  []  107.8 2.95 90 top
NOREF#12  -  []  171.9 53.12 0 top
NOREF#13  -  []  288.23 -4.22 90 top
NOREF#14  -  []  65.1 52.42 90 top
NOREF#15  -  []  241.12 164.37 0 top
NOREF#16  -  []  110.5 65.12 0 top
NOREF#17  -  []  296 16.59 90 top
NOREF#18  -  []  323.37 306.58 90 top
NOREF#19  -  []  59.9 216.3 0 top
NOREF#20  -  []  68.35 143.36 0 top
NOREF#21  -  []  143.9 53.12 0 top
NOREF#22  -  []  61 7.59 90 top
NOREF#23  -  []  240.4 16.59 90 top
NOREF#24  -  []  333.96 172.33 0 top
NOREF#25  -  []  201.8 2.95 90 top
NOREF#26  -  []  318.15 346.49 0 top
NOREF#27  -  []  284.9 53.12 0 top
NOREF#28  -  []  65.1 56.42 90 top
NOREF#29  -  []  382.23 -4.22 90 top
NOREF#30  -  []  234.09 304.73 90 top
NOREF#31  -  []  55.4 343.02 90 top
NOREF#32  -  []  381.4 7.59 90 top
NOREF#33  -  []  26.55 305.38 90 top
NOREF#34  -  []  386.13 197.2 90 top
NOREF#35  -  []  110.5 65.12 0 top
NOREF#36  -  []  381.4 25.59 90 top
NOREF#37  -  []  295.75 68.94 0 top
NOREF#38  -  []  240.4 34.59 90 top
NOREF#39  -  []  154.75 68.94 0 top
NOREF#40  -  []  145.26 305.33 90 top
NOREF#41  -  []  170.91 173.07 270 top
NOREF#42  -  []  146.4 16.59 90 top
NOREF#43  -  []  331.9 53.12 90 top
NOREF#44  -  []  336.84 308.14 0 top
NOREF#45  -  []  50.63 179.69 90 top
NOREF#46  -  []  228.51 307.53 0 top
NOREF#47  -  []  81.55 188.3 90 top
NOREF#48  -  []  344.46 149.2 90 top
NOREF#49  -  []  377.3 52.42 90 top
NOREF#50  -  []  81.99 362.77 0 top
NOREF#51  -  []  101.08 221.7 0 top
NOREF#52  -  []  326.68 168.46 90 top
NOREF#53  -  []  249.4 51.89 0 top
NOREF#54  -  []  155 25.59 90 top
NOREF#55  -  []  375.35 205.62 0 top
NOREF#56  -  []  319.57 308.83 0 top
NOREF#57  -  []  -65.21 389.21 0 top
NOREF#58  -  []  33.2 51.89 0 top
NOREF#59  -  []  327.78 346.49 0 top
NOREF#60  -  []  374.32 2 270 top
NOREF#61  -  []  98.8 2.95 90 top
NOREF#62  -  []  61.4 51.89 0 top
NOREF#63  -  []  333.98 342.89 90 top
NOREF#64  -  []  61 7.59 90 top
NOREF#65  -  []  127.2 51.89 0 top
NOREF#66  -  []  99.4 25.59 90 top
NOREF#67  -  []  362.2 51.89 0 top
NOREF#68  -  []  249 7.59 0 top
NOREF#69  -  []  333.96 179.68 90 top
NOREF#70  -  []  59.78 -4.22 0 top
NOREF#71  -  []  19.28 343 90 top
NOREF#72  -  []  236.16 108.82 270 top
NOREF#73  -  []  150.2 305.23 90 top
NOREF#74  -  []  89.08 214.1 90 top
NOREF#75  -  []  359.34 208.52 90 top
NOREF#76  -  []  135.33 305.23 90 top
NOREF#77  -  []  152.7 305.33 90 top
NOREF#78  -  []  338.77 106.98 90 top
NOREF#79  -  []  272.5 89.3 90 top
NOREF#80  -  []  296.4 51.89 0 top
NOREF#81  -  []  68.35 163.68 0 top
NOREF#82  -  []  -75.27 344.93 90 top
NOREF#83  -  []  406.59 37.35 0 top
NOREF#84  -  []  355.63 306.59 90 top
NOREF#85  -  []  -69.81 385.86 90 top
NOREF#86  -  []  18.1 52.42 90 top
NOREF#87  -  []  209.66 310.23 0 top
NOREF#88  -  []  32.31 347.34 0 top
NOREF#89  -  []  382.62 -4.22 0 top
NOREF#90  -  []  76.33 310.21 0 top
NOREF#91  -  []  108 7.59 0 top
NOREF#92  -  []  407.3 218.15 90 top
NOREF#93  -  []  221.2 51.89 0 top
NOREF#94  -  []  65.1 56.42 90 top
NOREF#95  -  []  386.6 198.75 90 top
NOREF#96  -  []  92.89 310.21 0 top
NOREF#97  -  []  143.9 53.12 0 top
NOREF#98  -  []  254.7 169.77 90 top
NOREF#99  -  []  423.07 -0.15 0 top
NOREF#100  -  []  61 34.59 90 top
NOREF#101  -  []  170.61 168.68 0 top
NOREF#102  -  []  251.5 65.12 0 top
NOREF#103  -  []  202.4 51.89 0 top
NOREF#104  -  []  60.8 2.95 90 top
NOREF#105  -  []  362.43 355.94 0 top
NOREF#106  -  []  304.65 68.94 0 top
NOREF#107  -  []  143.9 53.12 90 top
NOREF#108  -  []  204.5 65.12 0 top
NOREF#109  -  []  239.8 2.95 90 top
NOREF#110  -  []  43.35 351.6 0 top
NOREF#111  -  []  111.53 343.02 90 top
NOREF#112  -  []  248.75 68.94 0 top
NOREF#113  -  []  18.83 362.77 0 top
NOREF#114  -  []  150.29 209.14 90 top
NOREF#115  -  []  201.8 2.95 90 top
NOREF#116  -  []  16.5 53.12 90 top
NOREF#117  -  []  18.1 56.42 90 top
NOREF#118  -  []  14 45.29 90 top
NOREF#119  -  []  59.78 -4.22 0 top
NOREF#120  -  []  -8.78 39.94 0 top
NOREF#121  -  []  270.09 173.74 90 top
NOREF#122  -  []  38.42 113.06 0 top
NOREF#123  -  []  61 7.59 0 top
